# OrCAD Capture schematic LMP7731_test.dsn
size A4
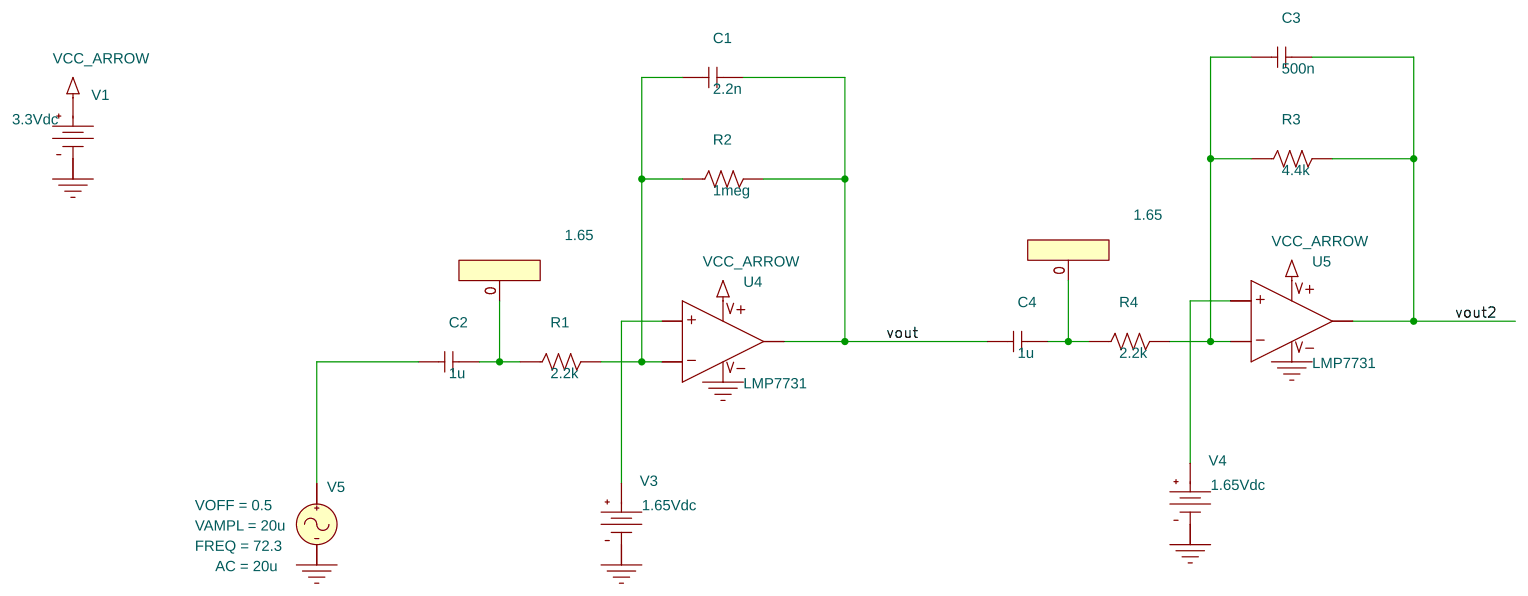
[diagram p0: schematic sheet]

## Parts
C1  2.2n  [cap196]
C2  1u  [cap196]
C3  500n  [cap196]
C4  1u  [cap196]
NS1  1.65
NS2  1.65
R1  2.2k  [AXRC05]
R2  1meg  [AXRC05]
R3  4.4k  [AXRC05]
R4  2.2k  [AXRC05]
U4  LMP7731
U5  LMP7731
V1  VDC
V3  VDC
V4  VDC
V5  VSIN

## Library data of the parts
C1-C4 = C
NS1 NS2 = NODESET1
R1-R4 = R
U4 U5 = LMP7731
V1 = VDC: DC: 3.3Vdc
V3 V4 = VDC: DC: 1.65Vdc
V5 = VSIN: AC: 20u; FREQ: 72.3; VAMPL: 20u; VOFF: 0.5

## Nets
VDD: U4.3(VCC) U5.3(VCC) V1.0(+)
0: U4.4(VEE) U5.4(VEE) V1.1(-) V3.1(-) V4.1(-) V5.2(-)
vout: C1.2 C4.1 R2.2 U4.5(OUT)
vout2: C3.2 R3.2 U5.5(OUT)
N09028: C3.1 R3.1 R4.2 U5.2(IN-)
N09044: C1.1 R1.2 R2.1 U4.2(IN-)
N09202: C4.2 NS2.0(+) R4.1
N09228: C2.2 NS1.0(+) R1.1
N09254: U5.1(IN+) V4.0(+)
N09264: U4.1(IN+) V3.0(+)
N09384: C2.1 V5.1(+)
